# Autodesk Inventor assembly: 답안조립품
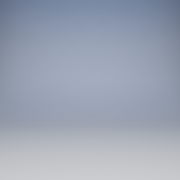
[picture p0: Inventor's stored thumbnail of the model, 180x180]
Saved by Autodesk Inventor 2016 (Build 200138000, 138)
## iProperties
Created: 2017-04
Part Number: 답안조립품
Material: 일반
Document SubType Name: Assembly
Designer: CAMTIC
Author: CAMTIC
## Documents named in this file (1)
- C:\Users\CAMTIC\Desktop\470407V1029\답안조립품.iam
